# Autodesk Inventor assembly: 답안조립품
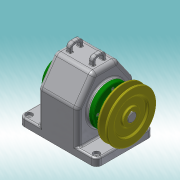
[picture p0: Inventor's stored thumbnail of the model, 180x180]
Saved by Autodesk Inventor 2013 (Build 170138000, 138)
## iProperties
Created: 2016-12
Part Number: 답안조립품
Document SubType Name: Assembly
Designer: dgall
Author: dgall
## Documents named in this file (15)
- C:\Users\dgall\Desktop\461207V1014\답안조립품.iam
- C:\Users\dgall\Desktop\461207V1014\본체.ipt
- C:\Users\dgall\Desktop\461207V1014\V-벨트풀리.ipt
- C:\Users\dgall\Desktop\461207V1014\뒤커버.ipt
- C:\Users\dgall\Desktop\461207V1014\멈춤나사 - M4x10.ipt
- C:\Users\dgall\Desktop\461207V1014\베어링 6203.ipt
- C:\Users\dgall\Desktop\461207V1014\볼트 M3 x 8.ipt
- C:\Users\dgall\Desktop\461207V1014\볼트 M3 x 10.ipt
- C:\Users\dgall\Desktop\461207V1014\부시.ipt
- C:\Users\dgall\Desktop\461207V1014\스퍼기어.ipt
- C:\Users\dgall\Desktop\461207V1014\앞커버.ipt
- C:\Users\dgall\Desktop\461207V1014\오일씰 28 40 8.ipt
- C:\Users\dgall\Desktop\461207V1014\축.ipt
- C:\Users\dgall\Desktop\461207V1014\키 - 5 x 5 x 18.ipt
- C:\Users\dgall\Desktop\461207V1014\키 - 6 x 6 x 22.ipt
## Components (9 placed, 3 different names)
1. V-벨트풀리:1
2. ISO 4762 M3 x 10:1
3. ISO 4762 M3 x 10:2
4. ISO 4762 M3 x 10:3
5. ISO 4762 M3 x 10:4
6. ISO 4762 M3 x 8:1
7. ISO 4762 M3 x 8:2
8. ISO 4762 M3 x 8:3
9. ISO 4762 M3 x 8:4
